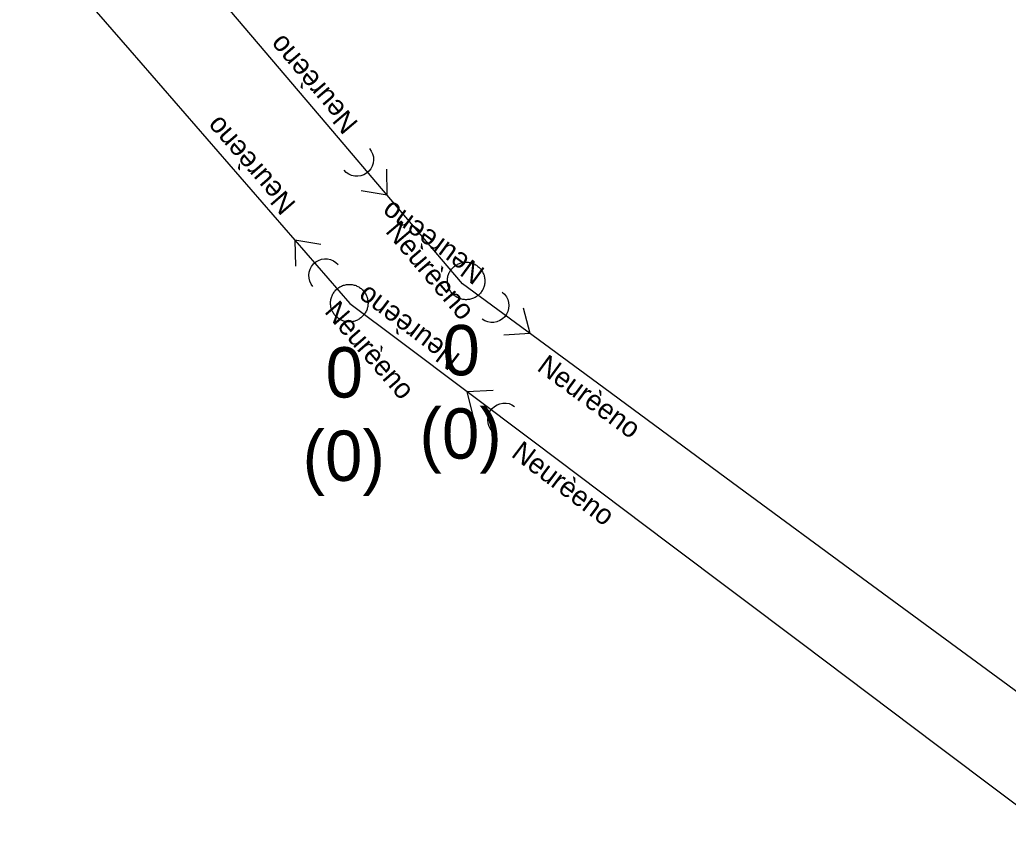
# Model space of a CAD drawing. Extents: x -606452 to -604459, y -1157823 to -1156972.
# Drawn here: x -605973.72 to -605960.54, y -1157495.22 to -1157484.22 of the extents above; entities that cross this region are included whole.
import ezdxf

# ---------------------------------------------------------------- set-up
doc = ezdxf.new("R2010")
doc.units = 0
doc.layers.add('Stoka', color=7, linetype='Continuous')
doc.layers.add('Vstupní šachta stoky', color=7, linetype='Continuous')

msp = doc.modelspace()

# ---------------------------------------------------------------- linework, layer by layer
at = {"layer": 'Stoka'}
for points in [[(-605973.721, -1157482.937), (-605972.254, -1157484.625)], [(-605969.548, -1157485.707), (-605970.996, -1157484.003)], [(-605972.254, -1157484.625), (-605970.787, -1157486.312)], [(-605968.1, -1157487.411), (-605969.548, -1157485.707)], [(-605969.058, -1157485.937), (-605969.034, -1157485.971), (-605969.017, -1157486.008), (-605969.007, -1157486.048), (-605969.005, -1157486.089), (-605969.01, -1157486.13), (-605969.022, -1157486.17), (-605969.042, -1157486.206), (-605969.068, -1157486.238), (-605969.1, -1157486.265), (-605969.135, -1157486.285), (-605969.174, -1157486.299), (-605969.215, -1157486.305), (-605969.256, -1157486.303), (-605969.297, -1157486.294), (-605969.335, -1157486.278), (-605969.369, -1157486.255), (-605969.398, -1157486.226)], [(-605970.787, -1157486.312), (-605969.32, -1157488)], [(-605968.822, -1157486.559), (-605968.827, -1157486.21)], [(-605968.822, -1157486.56), (-605969.168, -1157486.499)], [(-605970.055, -1157487.155), (-605969.709, -1157487.212)], [(-605970.055, -1157487.156), (-605970.046, -1157487.505)], [(-605969.812, -1157487.776), (-605969.837, -1157487.742), (-605969.854, -1157487.705), (-605969.864, -1157487.665), (-605969.867, -1157487.624), (-605969.862, -1157487.583), (-605969.85, -1157487.543), (-605969.831, -1157487.507), (-605969.805, -1157487.474), (-605969.774, -1157487.447), (-605969.739, -1157487.427), (-605969.7, -1157487.413), (-605969.659, -1157487.406), (-605969.618, -1157487.407), (-605969.577, -1157487.415), (-605969.539, -1157487.431), (-605969.505, -1157487.454), (-605969.475, -1157487.482)], [(-605967.82, -1157487.74), (-605968.1, -1157487.411)], [(-605966.019, -1157489.065), (-605967.82, -1157487.74)], [(-605967.29, -1157487.851), (-605967.26, -1157487.878), (-605967.234, -1157487.911), (-605967.215, -1157487.948), (-605967.204, -1157487.987), (-605967.199, -1157488.028), (-605967.203, -1157488.069), (-605967.213, -1157488.109), (-605967.231, -1157488.146), (-605967.256, -1157488.18), (-605967.286, -1157488.208), (-605967.321, -1157488.23), (-605967.359, -1157488.245), (-605967.399, -1157488.253), (-605967.441, -1157488.254), (-605967.481, -1157488.247), (-605967.52, -1157488.232), (-605967.555, -1157488.211)], [(-605969.32, -1157488), (-605968.651, -1157488.503)], [(-605966.918, -1157488.402), (-605967.003, -1157488.063)], [(-605966.918, -1157488.403), (-605967.268, -1157488.424)], [(-605968.651, -1157488.503), (-605966.864, -1157489.847)], [(-605964.218, -1157490.39), (-605966.019, -1157489.065)], [(-605967.759, -1157489.174), (-605967.409, -1157489.157)], [(-605967.759, -1157489.175), (-605967.677, -1157489.515)], [(-605967.392, -1157489.73), (-605967.423, -1157489.703), (-605967.448, -1157489.67), (-605967.466, -1157489.633), (-605967.478, -1157489.593), (-605967.481, -1157489.552), (-605967.478, -1157489.511), (-605967.467, -1157489.471), (-605967.448, -1157489.434), (-605967.423, -1157489.401), (-605967.393, -1157489.373), (-605967.358, -1157489.352), (-605967.319, -1157489.337), (-605967.279, -1157489.329), (-605967.238, -1157489.329), (-605967.197, -1157489.336), (-605967.159, -1157489.351), (-605967.123, -1157489.373)], [(-605966.864, -1157489.847), (-605965.076, -1157491.19)], [(-605962.417, -1157491.716), (-605964.218, -1157490.39)], [(-605965.076, -1157491.19), (-605963.289, -1157492.534)], [(-605960.616, -1157493.041), (-605962.417, -1157491.716)], [(-605963.289, -1157492.534), (-605961.502, -1157493.878)], [(-605959.19, -1157494.09), (-605960.616, -1157493.041)], [(-605961.502, -1157493.878), (-605959.715, -1157495.222)]]:
    msp.add_lwpolyline(points, dxfattribs=at)
at = {"layer": 'Vstupní šachta stoky'}
for p, q in [((-605967.783, -1157487.451), (-605967.77, -1157487.451)), ((-605969.341, -1157487.747), (-605969.328, -1157487.747))]:
    msp.add_line(p, q, dxfattribs=at)
for points in [[(-605967.77, -1157487.451), (-605967.757, -1157487.451), (-605967.744, -1157487.452), (-605967.731, -1157487.454), (-605967.718, -1157487.457), (-605967.705, -1157487.46), (-605967.692, -1157487.463), (-605967.68, -1157487.468), (-605967.668, -1157487.473), (-605967.656, -1157487.479), (-605967.644, -1157487.485), (-605967.633, -1157487.492), (-605967.622, -1157487.5), (-605967.612, -1157487.508), (-605967.602, -1157487.516), (-605967.592, -1157487.525), (-605967.583, -1157487.535), (-605967.575, -1157487.545), (-605967.567, -1157487.556), (-605967.559, -1157487.567), (-605967.552, -1157487.578), (-605967.546, -1157487.59), (-605967.541, -1157487.602), (-605967.536, -1157487.614), (-605967.531, -1157487.626), (-605967.528, -1157487.639), (-605967.525, -1157487.652), (-605967.523, -1157487.665), (-605967.521, -1157487.678), (-605967.52, -1157487.691), (-605967.52, -1157487.704), (-605967.521, -1157487.718), (-605967.522, -1157487.731), (-605967.524, -1157487.744), (-605967.526, -1157487.757), (-605967.53, -1157487.769), (-605967.533, -1157487.782), (-605967.538, -1157487.794), (-605967.543, -1157487.807), (-605967.549, -1157487.818), (-605967.556, -1157487.83), (-605967.563, -1157487.841), (-605967.57, -1157487.852), (-605967.579, -1157487.862), (-605967.587, -1157487.872), (-605967.597, -1157487.881), (-605967.607, -1157487.89), (-605967.617, -1157487.899), (-605967.627, -1157487.906), (-605967.638, -1157487.914), (-605967.65, -1157487.92), (-605967.662, -1157487.926), (-605967.674, -1157487.932), (-605967.686, -1157487.936), (-605967.698, -1157487.941), (-605967.711, -1157487.944), (-605967.724, -1157487.947), (-605967.737, -1157487.949), (-605967.75, -1157487.95), (-605967.763, -1157487.951), (-605967.777, -1157487.951), (-605967.79, -1157487.95), (-605967.803, -1157487.949), (-605967.816, -1157487.947), (-605967.829, -1157487.944), (-605967.842, -1157487.941), (-605967.854, -1157487.936), (-605967.866, -1157487.932), (-605967.878, -1157487.926), (-605967.89, -1157487.92), (-605967.902, -1157487.914), (-605967.913, -1157487.906), (-605967.923, -1157487.899), (-605967.933, -1157487.89), (-605967.943, -1157487.881), (-605967.953, -1157487.872), (-605967.961, -1157487.862), (-605967.97, -1157487.852), (-605967.977, -1157487.841), (-605967.984, -1157487.83), (-605967.991, -1157487.818), (-605967.997, -1157487.807), (-605968.002, -1157487.794), (-605968.007, -1157487.782), (-605968.01, -1157487.769), (-605968.014, -1157487.757), (-605968.016, -1157487.744), (-605968.018, -1157487.731), (-605968.019, -1157487.718), (-605968.02, -1157487.704), (-605968.02, -1157487.691), (-605968.019, -1157487.678), (-605968.017, -1157487.665), (-605968.015, -1157487.652), (-605968.012, -1157487.639), (-605968.009, -1157487.626), (-605968.004, -1157487.614), (-605967.999, -1157487.602), (-605967.994, -1157487.59), (-605967.988, -1157487.578), (-605967.981, -1157487.567)], [(-605967.981, -1157487.567), (-605967.973, -1157487.556), (-605967.965, -1157487.545), (-605967.957, -1157487.535), (-605967.948, -1157487.525), (-605967.938, -1157487.516), (-605967.928, -1157487.508), (-605967.918, -1157487.5), (-605967.907, -1157487.492), (-605967.896, -1157487.485), (-605967.884, -1157487.479), (-605967.872, -1157487.473), (-605967.86, -1157487.468), (-605967.848, -1157487.463), (-605967.835, -1157487.46), (-605967.822, -1157487.457), (-605967.809, -1157487.454), (-605967.796, -1157487.452), (-605967.783, -1157487.451)], [(-605969.328, -1157487.747), (-605969.315, -1157487.747), (-605969.302, -1157487.748), (-605969.289, -1157487.75), (-605969.276, -1157487.753), (-605969.263, -1157487.756), (-605969.25, -1157487.759), (-605969.238, -1157487.764), (-605969.226, -1157487.769), (-605969.214, -1157487.775), (-605969.202, -1157487.781), (-605969.191, -1157487.788), (-605969.18, -1157487.796), (-605969.17, -1157487.804), (-605969.16, -1157487.812), (-605969.15, -1157487.821), (-605969.141, -1157487.831), (-605969.133, -1157487.841), (-605969.125, -1157487.852), (-605969.117, -1157487.863), (-605969.11, -1157487.874), (-605969.104, -1157487.886), (-605969.099, -1157487.898), (-605969.094, -1157487.91), (-605969.089, -1157487.922), (-605969.086, -1157487.935), (-605969.083, -1157487.948), (-605969.081, -1157487.961), (-605969.079, -1157487.974), (-605969.078, -1157487.987), (-605969.078, -1157488), (-605969.079, -1157488.014), (-605969.08, -1157488.027), (-605969.082, -1157488.04), (-605969.084, -1157488.053), (-605969.088, -1157488.065), (-605969.091, -1157488.078), (-605969.096, -1157488.09), (-605969.101, -1157488.103), (-605969.107, -1157488.114), (-605969.114, -1157488.126), (-605969.121, -1157488.137), (-605969.128, -1157488.148), (-605969.137, -1157488.158), (-605969.145, -1157488.168), (-605969.155, -1157488.177), (-605969.165, -1157488.186), (-605969.175, -1157488.195), (-605969.185, -1157488.202), (-605969.196, -1157488.21), (-605969.208, -1157488.216), (-605969.22, -1157488.222), (-605969.232, -1157488.228), (-605969.244, -1157488.232), (-605969.256, -1157488.237), (-605969.269, -1157488.24), (-605969.282, -1157488.243), (-605969.295, -1157488.245), (-605969.308, -1157488.246), (-605969.321, -1157488.247), (-605969.335, -1157488.247), (-605969.348, -1157488.246), (-605969.361, -1157488.245), (-605969.374, -1157488.243), (-605969.387, -1157488.24), (-605969.4, -1157488.237), (-605969.412, -1157488.232), (-605969.424, -1157488.228), (-605969.436, -1157488.222), (-605969.448, -1157488.216), (-605969.46, -1157488.21), (-605969.471, -1157488.202), (-605969.481, -1157488.195), (-605969.491, -1157488.186), (-605969.501, -1157488.177), (-605969.511, -1157488.168), (-605969.519, -1157488.158), (-605969.528, -1157488.148), (-605969.535, -1157488.137), (-605969.542, -1157488.126), (-605969.549, -1157488.114), (-605969.555, -1157488.103), (-605969.56, -1157488.09), (-605969.565, -1157488.078), (-605969.568, -1157488.065), (-605969.572, -1157488.053), (-605969.574, -1157488.04), (-605969.576, -1157488.027), (-605969.577, -1157488.014), (-605969.578, -1157488), (-605969.578, -1157487.987), (-605969.577, -1157487.974), (-605969.575, -1157487.961), (-605969.573, -1157487.948), (-605969.57, -1157487.935), (-605969.567, -1157487.922), (-605969.562, -1157487.91), (-605969.557, -1157487.898), (-605969.552, -1157487.886), (-605969.546, -1157487.874), (-605969.539, -1157487.863)], [(-605969.539, -1157487.863), (-605969.531, -1157487.852), (-605969.523, -1157487.841), (-605969.515, -1157487.831), (-605969.506, -1157487.821), (-605969.496, -1157487.812), (-605969.486, -1157487.804), (-605969.476, -1157487.796), (-605969.465, -1157487.788), (-605969.454, -1157487.781), (-605969.442, -1157487.775), (-605969.43, -1157487.769), (-605969.418, -1157487.764), (-605969.406, -1157487.759), (-605969.393, -1157487.756), (-605969.38, -1157487.753), (-605969.367, -1157487.75), (-605969.354, -1157487.748), (-605969.341, -1157487.747)]]:
    msp.add_lwpolyline(points, dxfattribs=at)

# ---------------------------------------------------------------- texts
at = {"layer": 'Stoka'}
for rotation, p in [(130.3565, (-605969.196, -1157485.596)), (130.9977, (-605970.026, -1157486.67)), (143.6542, (-605967.503, -1157487.551)), (310.3565, (-605968.857, -1157487.045)), (143.0628, (-605967.832, -1157488.694)), (310.9977, (-605969.67, -1157488.115)), (323.6542, (-605966.84, -1157488.883)), (323.0629, (-605967.182, -1157490.032))]:
    msp.add_text('Neurèeno', height=0.2683, rotation=rotation, dxfattribs=at).set_placement(p)
at = {"layer": 'Vstupní šachta stoky'}
for s, height, p in [('0', 0.671, (-605968.086, -1157488.959)), ('0', 0.671, (-605969.644, -1157489.255)), ('(0)', 0.6708, (-605968.392, -1157490.07)), ('(0)', 0.6708, (-605969.95, -1157490.366))]:
    msp.add_text(s, height=height, dxfattribs=at).set_placement(p)

doc.saveas('drawing.dxf')
